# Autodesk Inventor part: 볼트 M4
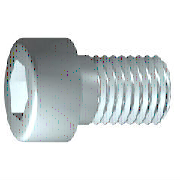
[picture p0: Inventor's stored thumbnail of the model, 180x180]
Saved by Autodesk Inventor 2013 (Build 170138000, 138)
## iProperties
IsCustomPart: 0
Created: 2018-09
Part Number: 볼트 M4
Material: 스테인리스강
Description: 6각머리 태핑 나사
Document SubType Name: Modeling
Standard: KS B 1003
Standards Organization: KS
Language: ko-KR
Size Designation: M 4 x 10
Categories: <MemberInstance><Categories><Category DisplayName="조임쇠" InternalName="e4da775c-781d-43d5-af7c-5136215cf5a6" Mnemonic="FSTN"><Category DisplayName="볼트" InternalN
Density: 8.08 g/cm^3
Mass: 2.09412 g
Surface Area: 3.0572 cm^2
Volume: 0.259174 cm^3
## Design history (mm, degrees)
sketch "스케치1"
  geometry: L1 (-1, 0)-(10, 0); L2 (10, 0)-(10, 2); L3 (10, 2)-(1.75, 2); L4 (1.75, 2)-(1.32, 2); L5 (1.32, 2)-(0, 2); L6 (0, 2)-(0, 3.5); L7 (0, 3.5)-(-4, 3.5); L8 (-4, 3.5)-(-4, 1.732); L9 (-4, 1.732)-(-2, 1.732); L10 (-2, 1.732)-(-1, 0); L11 (-6.8, 0)-(12.8, 0) reference; L12 (0, -0.7)-(0, 4.2) reference; L13 (1.75, 2)-(0, 2)
  constraints: 22 end point, 6 parallel, 2 collinear, 2 perpendicular, 1 horizontal, 1 point on line
  dimensions: "d1" = 8.25 distance from line of L3.end L2 (= GEL); "d2" = 0.42952 distance of L4.end L3.end (computed from GAL); "d3" = 4 distance between parallel lines of L8 L6 (= KOH); "d4" = 2 distance of L8.end L9.end (= INTI); "d5" = 60 deg angle of L10 L1; "d6" = 4 diameter of L3 L1 (= GD); "d7" = 4 diameter of L5 L1 (= BDM); "d8" = 3.4641 diameter of L9 L1 (= 1.1547 x SW); "d9" = 7 diameter of L7 L1 (= KOD); "d26" = 10 distance between parallel lines of L12 L2 (= NLG)
revolve "본체" sketch "스케치1" stored, may be unused: angle "d10" = 90 deg
sketch "스케치2"
  geometry: L1 (0, -4.9)-(0, 4.9) reference; L2 (-4.9, 0)-(4.9, 0) reference; L3 (1.732, 0)-(0.866, -1.5); L4 (0.866, -1.5)-(-0.866, -1.5); L5 (-0.866, -1.5)-(-1.732, 0); L6 (-1.732, 0)-(-0.866, 1.5); L7 (-0.866, 1.5)-(0.866, 1.5); L8 (0.866, 1.5)-(1.732, 0); 2 further points
  constraints: 12 end point, 1 coincident, 1 horizontal alignment, 1 point on line, 12 other
extrude "슬롯" join sketch "스케치2" stored distance "d11" = 10; taper "d12" = 0 deg
workplane "Work Plane1"
fillet "Fillet2" dims "d30" = 0.1 (= R)
body "Solid1"
fillet "모깎기1" dims "d17" = 0.4 (= RR)
feature "스레드" dims "d13" = 8.25 (= GEL), "d14" = 0
chamfer "모따기1" distance "d15" = 0.42941 (= -0.5 x SPD + 0.5 x GD); stored, may be unused: second distance "d16" = 0.42941 (= GUL), angle "d27" = 45 deg
other parameters: "GD" = 4 (= NND) [user parameter; used in 2 equation terms], "NLG" = 10 [user parameter; used in 1 equation term], "GEL" = 8.25 [user parameter; used in 2 equation terms], "KOD" = 7 [user parameter; used in 1 equation term], "KOH" = 4 [user parameter; used in 1 equation term], "INTI" = 2 [user parameter; used in 1 equation term], "GAL" = 0.42941 (= 0.61345 x PTC) [user parameter; used in 1 equation term], "GUL" = 0.42941 (= 0.61345 x PTC) [user parameter; used in 1 equation term], "BDM" = 4 (= NND) [user parameter; used in 1 equation term], "SW" = 3 [user parameter; used in 2 equation terms], "RR" = 0.4 [user parameter; used in 1 equation term], "SPD" = 3.14117 (= NND - 1.2269 x PTC) [user parameter; used in 1 equation term], "d19" = 0, "d28" = 0, "d29" = 0, "R" = 0.1 [user parameter; used in 1 equation term], "PHH" = 0.2 [user parameter], "GD1" = 3.14117 (= THREADDIA - 1.2269 x PTC) [user parameter], "THREADDIA" = 4 [user parameter; used in 1 equation term], "FAWI" = 45 deg [user parameter], "TPU" = 14.28571 (computed from PTC) [user parameter], "PTC" = 0.7 [user parameter; used in 5 equation terms], "NND" = 4 [user parameter; used in 3 equation terms], "TOA" = 30 deg [user parameter], "E0" = 3.465 (= 1.155 x SW) [user parameter]
